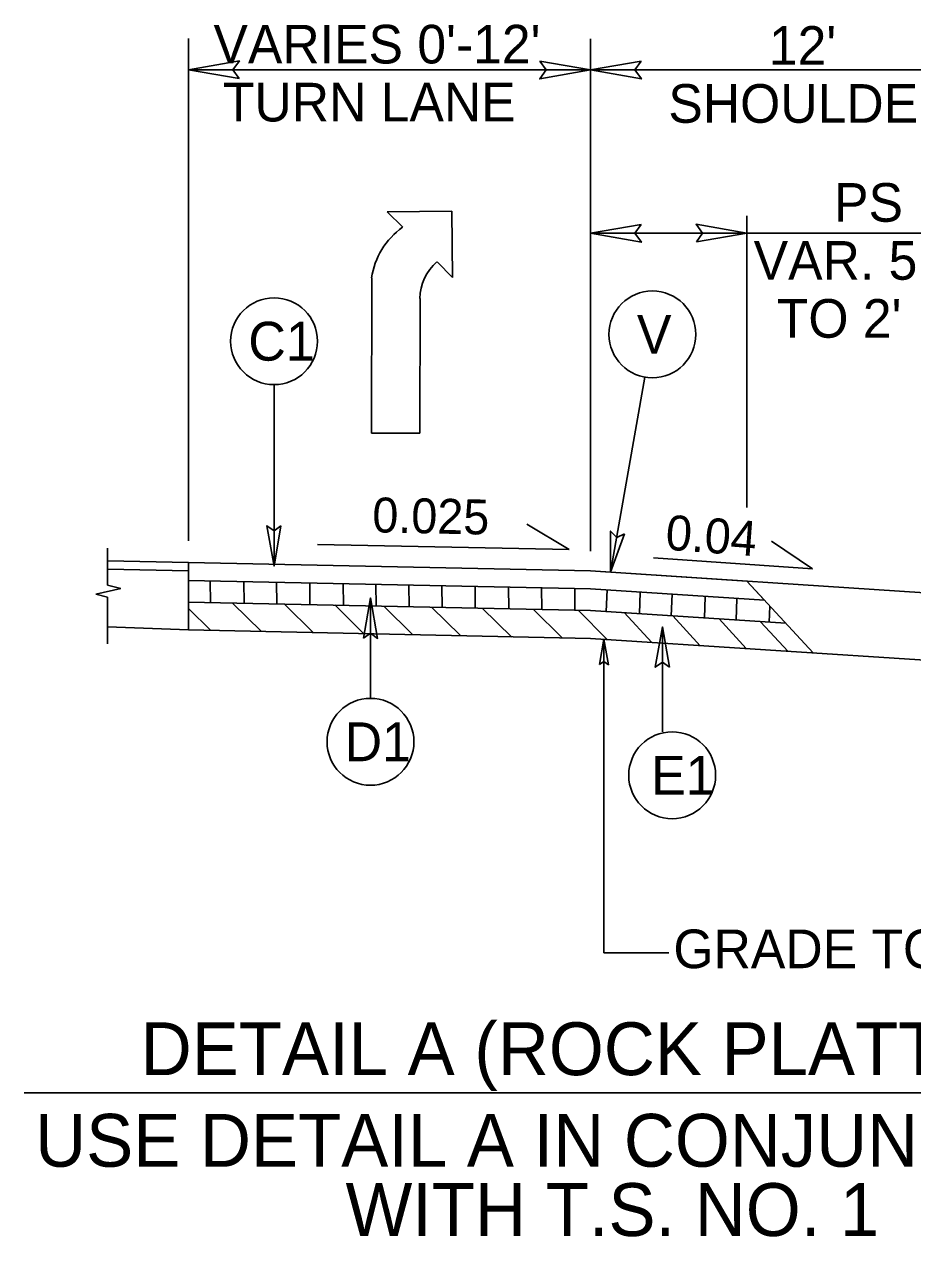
# Model space of a CAD drawing. Extents: x 2176024 to 2177225, y 75947 to 76635.
# Drawn here: x 2176808.93 to 2176835.45, y 76369 to 76405.18 of the extents above; entities that cross this region are included whole.
import ezdxf

# ---------------------------------------------------------------- set-up
doc = ezdxf.new("R2010")
doc.units = 0
for name, color, linetype in [('Exist XS Ground Line', 7, 'Continuous'), ('Old_Level_1', 7, 'Continuous'), ('Old_Level_11', 7, 'Continuous'), ('Old_Level_3', 7, 'Continuous'), ('Prop Dimension', 7, 'Continuous'), ('Prop Lane Arrow CELL', 7, 'Continuous'), ('Typical Curb CELL', 7, 'Continuous'), ('Typical Pavement Slope CELL', 7, 'Continuous'), ('Typical Pavement Slope Information CELL', 7, 'Continuous'), ('Typical Shoulder Slope CELL', 7, 'Continuous'), ('Typical Slope Point Local CELL', 7, 'Continuous'), ('Typical Terminator CELL', 7, 'Continuous'), ('Typical Text General CELL', 7, 'Continuous')]:
    doc.layers.add(name, color=color, linetype=linetype)

msp = doc.modelspace()

# ---------------------------------------------------------------- linework, layer by layer
at = {"layer": 'Exist XS Ground Line'}
msp.add_line((2176811.42, 76387.202), (2176813.835, 76387.105), dxfattribs=at)
at = {"layer": 'Old_Level_1'}
for p, q in [((2176814.49, 76387.918), (2176814.485, 76388.567)), ((2176815.496, 76387.893), (2176815.491, 76388.546)), ((2176816.47, 76387.881), (2176816.465, 76388.526)), ((2176817.46, 76387.852), (2176817.454, 76388.506)), ((2176818.457, 76387.845), (2176818.451, 76388.485)), ((2176819.436, 76387.824), (2176819.431, 76388.464)), ((2176820.417, 76387.804), (2176820.412, 76388.444)), ((2176821.406, 76387.779), (2176821.401, 76388.423)), ((2176822.395, 76387.76), (2176822.39, 76388.403)), ((2176823.393, 76387.736), (2176823.387, 76388.382)), ((2176824.382, 76387.723), (2176824.376, 76388.361)), ((2176825.369, 76387.695), (2176825.364, 76388.335)), ((2176826.305, 76387.656), (2176826.328, 76388.299)), ((2176827.292, 76387.588), (2176827.315, 76388.234)), ((2176828.247, 76387.531), (2176828.27, 76388.171)), ((2176829.234, 76387.459), (2176829.258, 76388.106)), ((2176830.184, 76387.398), (2176830.207, 76388.044)), ((2176814.506, 76387.091), (2176813.837, 76387.749)), ((2176816.016, 76387.054), (2176815.149, 76387.906)), ((2176817.565, 76387.015), (2176816.696, 76387.87)), ((2176819.063, 76387), (2176818.199, 76387.85)), ((2176820.521, 76386.973), (2176819.663, 76387.816)), ((2176821.951, 76386.936), (2176821.085, 76387.788)), ((2176823.487, 76386.886), (2176822.604, 76387.753)), ((2176824.986, 76386.87), (2176824.119, 76387.722)), ((2176826.336, 76386.822), (2176825.462, 76387.696)), ((2176827.661, 76386.732), (2176826.842, 76387.628)), ((2176831.171, 76387.341), (2176831.189, 76387.819)), ((2176829.106, 76386.634), (2176828.288, 76387.528)), ((2176830.48, 76386.549), (2176829.673, 76387.432)), ((2176831.736, 76386.461), (2176830.909, 76387.351)), ((2176808.932, 76373.293), (2176843.969, 76373.293))]:
    msp.add_line(p, q, dxfattribs=at)
at = {"layer": 'Old_Level_11'}
for p, q in [((2176827.457, 76394.649), (2176826.433, 76388.83)), ((2176816.389, 76394.424), (2176816.389, 76389.009)), ((2176819.267, 76385.064), (2176819.267, 76388.06)), ((2176827.981, 76384.065), (2176827.981, 76387.198))]:
    msp.add_line(p, q, dxfattribs=at)
for points in [[(2176816.595, 76390.209), (2176816.389, 76389.009), (2176816.175, 76390.216), (2176816.389, 76390.063)], [(2176826.845, 76389.976), (2176826.433, 76388.83), (2176826.432, 76390.055), (2176826.616, 76389.867)], [(2176819.06, 76386.86), (2176819.267, 76388.06), (2176819.48, 76386.854), (2176819.267, 76387.007)], [(2176828.188, 76385.998), (2176827.981, 76387.198), (2176827.768, 76385.991), (2176827.981, 76386.144)]]:
    msp.add_lwpolyline(points, close=True, dxfattribs=at)
for centre in [(2176827.682, 76395.925), (2176816.389, 76395.72), (2176819.267, 76383.768), (2176828.272, 76382.769)]:
    msp.add_circle(centre, 1.296, dxfattribs=at)
at = {"layer": 'Prop Dimension'}
for p, q in [((2176813.835, 76389.768), (2176813.835, 76404.752)), ((2176825.835, 76389.454), (2176825.835, 76404.742)), ((2176825.835, 76403.815), (2176813.835, 76403.815)), ((2176825.835, 76403.815), (2176837.835, 76403.815)), ((2176830.505, 76390.76), (2176830.505, 76399.457)), ((2176825.835, 76398.942), (2176837.101, 76398.942)), ((2176826.234, 76386.828), (2176826.234, 76377.473)), ((2176828.168, 76377.473), (2176826.234, 76377.473))]:
    msp.add_line(p, q, dxfattribs=at)
at = {"layer": 'Prop Lane Arrow CELL'}
for p, q in [((2176819.768, 76399.581), (2176821.699, 76399.599)), ((2176820.228, 76399.119), (2176819.768, 76399.581)), ((2176821.699, 76399.599), (2176821.717, 76397.625)), ((2176821.717, 76397.625), (2176821.257, 76398.086)), ((2176819.295, 76392.978), (2176819.304, 76397.607)), ((2176820.751, 76396.99), (2176820.743, 76392.975)), ((2176820.743, 76392.975), (2176819.295, 76392.978))]:
    msp.add_line(p, q, dxfattribs=at)
for centre, radius, start, end in [((2176821.574, 76397.255), 2.305, 125.9059, 171.2176), ((2176822.18, 76396.992), 1.437, 130.2355, 179.8937)]:
    msp.add_arc(centre, radius, start, end, dxfattribs=at)
at = {"layer": 'Typical Curb CELL'}
msp.add_line((2176813.835, 76387.105), (2176813.835, 76389.119), dxfattribs=at)
at = {"layer": 'Typical Pavement Slope CELL'}
for p, q in [((2176811.42, 76389.541), (2176811.42, 76388.441)), ((2176813.835, 76389.119), (2176811.42, 76389.169)), ((2176813.835, 76388.869), (2176811.42, 76388.919)), ((2176835.816, 76388.214), (2176825.835, 76388.869)), ((2176811.814, 76388.342), (2176811.07, 76388.17)), ((2176811.42, 76388.441), (2176811.814, 76388.342)), ((2176813.835, 76388.581), (2176825.835, 76388.331)), ((2176830.505, 76388.563), (2176832.477, 76386.419)), ((2176811.07, 76388.17), (2176811.42, 76388.084)), ((2176811.42, 76388.084), (2176811.42, 76386.691)), ((2176825.835, 76388.331), (2176831.032, 76387.99)), ((2176813.835, 76387.937), (2176825.835, 76387.687)), ((2176825.835, 76387.687), (2176831.662, 76387.305)), ((2176825.835, 76386.855), (2176846.757, 76385.482))]:
    msp.add_line(p, q, dxfattribs=at)
at = {"layer": 'Typical Pavement Slope Information CELL'}
for p, q in [((2176825.194, 76389.501), (2176823.933, 76390.263)), ((2176825.194, 76389.501), (2176817.688, 76389.651)), ((2176832.462, 76388.929), (2176831.24, 76389.751)), ((2176832.462, 76388.929), (2176827.717, 76389.255))]:
    msp.add_line(p, q, dxfattribs=at)
at = {"layer": 'Typical Shoulder Slope CELL'}
msp.add_line((2176813.835, 76387.105), (2176825.835, 76386.855), dxfattribs=at)
at = {"layer": 'Typical Slope Point Local CELL'}
for p, q in [((2176813.835, 76389.119), (2176811.42, 76389.169)), ((2176811.42, 76389.169), (2176811.42, 76388.919)), ((2176813.835, 76389.119), (2176825.835, 76388.869)), ((2176825.835, 76388.869), (2176813.835, 76389.119)), ((2176813.835, 76389.119), (2176813.835, 76388.581)), ((2176813.835, 76388.869), (2176813.835, 76389.119)), ((2176811.42, 76388.919), (2176813.835, 76388.869)), ((2176830.505, 76388.563), (2176825.835, 76388.869)), ((2176813.835, 76388.581), (2176825.835, 76388.331)), ((2176831.032, 76387.99), (2176830.505, 76388.563)), ((2176825.835, 76388.331), (2176831.032, 76387.99))]:
    msp.add_line(p, q, dxfattribs=at)
at = {"layer": 'Typical Terminator CELL'}
for points in [[(2176815.344, 76403.555), (2176813.835, 76403.815), (2176815.353, 76404.083), (2176815.16, 76403.815)], [(2176824.325, 76404.075), (2176825.835, 76403.815), (2176824.317, 76403.546), (2176824.51, 76403.815)], [(2176827.344, 76404.075), (2176825.835, 76403.815), (2176827.353, 76403.546), (2176827.16, 76403.815)], [(2176827.344, 76399.202), (2176825.835, 76398.942), (2176827.353, 76398.674), (2176827.16, 76398.942)], [(2176828.996, 76398.683), (2176830.505, 76398.942), (2176828.987, 76399.211), (2176829.18, 76398.942)], [(2176826.104, 76386.074), (2176826.234, 76386.828), (2176826.369, 76386.069), (2176826.234, 76386.166)]]:
    msp.add_lwpolyline(points, close=True, dxfattribs=at)

# ---------------------------------------------------------------- texts
at = {"layer": 'Old_Level_11'}
for s, p in [('C1', (2176815.62, 76395.14)), ('V', (2176827.218, 76395.345)), ('D1', (2176818.494, 76383.188)), ('E1', (2176827.643, 76382.189))]:
    msp.add_text(s, height=1.16, rotation=0.0003, dxfattribs=at).set_placement(p)
at = {"layer": 'Old_Level_3'}
for s, p in [('DETAIL A (ROCK PLATTING)', (2176812.408, 76373.821)), ('USE DETAIL A IN CONJUNCTION', (2176809.256, 76371.089)), ('WITH T.S. NO. 1', (2176818.524, 76369.022))]:
    msp.add_text(s, height=1.5766, rotation=0, dxfattribs=at).set_placement(p)
at = {"layer": 'Typical Pavement Slope Information CELL'}
for s, rotation, p in [('0.025', 358.8543, (2176819.314, 76390.019)), ('0.04', 355.7342, (2176828.051, 76389.504))]:
    msp.add_text(s, height=1.0429, rotation=rotation, dxfattribs=at).set_placement(p)
at = {"layer": 'Typical Text General CELL'}
for s, height, p in [("VARIES 0'-12'", 1.15334, (2176814.58, 76404.007)), ("12' ", 1.1533, (2176831.159, 76403.968)), (' TURN LANE', 1.1533, (2176814.433, 76402.277)), ('SHOULDER', 1.1533, (2176828.158, 76402.238)), ('PS', 1.1533, (2176833.105, 76399.285)), ("VAR. 5.6'", 1.1533, (2176830.705, 76397.555)), (" TO 2'", 1.1533, (2176830.966, 76395.824)), ('GRADE TO THIS LINE', 1.15334, (2176828.308, 76377.013))]:
    msp.add_text(s, height=height, dxfattribs=at).set_placement(p)

doc.saveas('drawing.dxf')
